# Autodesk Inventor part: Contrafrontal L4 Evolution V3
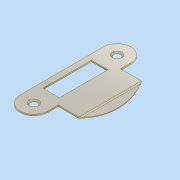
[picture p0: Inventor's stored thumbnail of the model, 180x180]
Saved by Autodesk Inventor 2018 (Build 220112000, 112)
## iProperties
Created: 2020-04
Part Number: Contrafrontal L4 Evolution V3
Material: Acero inoxidable
Document SubType Name: Modeling
Designer: PROYECTO
Density: 8 g/cm^3
Appearance: Titanio
Author: PROYECTO
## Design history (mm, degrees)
sketch "Boceto1"
  geometry: L1 (0, 0)-(0, 60); L2 (-10, 60)-(-10, 0); L3 (-6, 47.5)-(-6, 12.5); L4 (-6, 12.5)-(6, 12.5); L5 (6, 12.5)-(6, 47.5); L6 (6, 47.5)-(-6, 47.5); L7 (-6, 47.5)-(6, 12.5); L8 (-6, 12.5)-(6, 47.5); L9 (10, 52.5)-(25, 52.5); L10 (10, 7.5)-(25, 7.5); L11 (25, 52.5)-(25, 7.5); L12 (10, 0)-(10, 7.5); L13 (10, 52.5)-(10, 60); C1 r 2.5 at (0, 60); C2 r 2.5 at (0, 0); A1 r 10 centre (0, 0) between (-10, 0) and (10, 0); A2 r 10 centre (0, 60) between (10, 60) and (-10, 60); 1 further point
  constraints: 28 end point, 6 tangent, 4 centre point, 4 parallel, 4 point on circle, 3 horizontal, 3 midpoint, 2 coincident, 1 perpendicular, 1 vertical
  dimensions: "d1" = 12 distance of L5.end L3.start; "d2" = 35 distance of L4.end L5.end; "d3" = 60 distance of L1.start L1.end; "d4" = 5 diameter of C1; "d5" = 5 diameter of C2; "d7" = 45 distance between parallel lines of L10 L9; "d17" = 7.5 distance from line of L1.start L10; "d18" = 20 distance between parallel lines of L2 L13; "d19" = 35 distance between parallel lines of L2 L11
extrude "Extrusión1" new body sketch "Boceto1" distance "d11" = 1; taper "d12" = 0 deg
chamfer "Chaflán1" distance "d13" = 1; stored, may be unused: second distance "d14" = 2, angle "d15" = 45 deg
sketch "Boceto2"
  geometry: L1 (25, 52.5)-(25, 7.5) reference; A1 r 45 centre (-13.971, 30) between (25, 7.5) and (25, 52.5); 1 further point
  constraints: 2 point on circle, 1 centre point
  dimensions: "d20" = 45 radius of A1
extrude "Extrusión2" join sketch "Boceto2" distance "d21" = 1; taper "d22" = 0 deg
sketch "Boceto4"
  geometry: L1 (-25, 52.5)-(-25, 7.5); A1 r 45 centre (13.971, 30) between (-25, 52.5) and (-25, 7.5) reference; 1 further point
  constraints: 2 end point, 1 vertical
feature "Pieza de plegado1" sketch "Boceto4" dims "d23" = 2, "d24" = 25 deg
node "Sólido1"
other parameters: "d0" = 16
